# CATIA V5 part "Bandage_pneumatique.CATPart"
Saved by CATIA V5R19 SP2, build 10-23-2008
Part number: Bandage_pneumatique
Bounding box of the stored display mesh (mm): x -331.971 to 331.971, y -970.5 to -729.5, z -331.971 to 331.971
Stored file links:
  G:\EU_thinkMotion\CFAO_2010\MMS_groupe3\MMS_groupe3\pmayet\pmayet_assemblage_animation\pmayet_assemblage_animation\Bandage_pneumatique.CATPart
  G:\EU_thinkMotion\CFAO_2010\MMS_groupe3\MMS_groupe3\pmayet\pmayet_assemblage_animation\pmayet_assemblage_animation\pmayet_assemblage_animation.CATProduct
  G:\EU_thinkMotion\CFAO_2010\MMS_groupe3\MMS_groupe3\pmayet\pmayet_assemblage_animation\pmayet_assemblage_animation\Squelette_porte_moyeu.CATPart
  G:\EU_thinkMotion\CFAO_2010\MMS_groupe3\MMS_groupe3\pmayet\pmayet_assemblage_animation\pmayet_assemblage_animation\Jante.CATPart
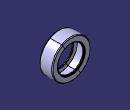
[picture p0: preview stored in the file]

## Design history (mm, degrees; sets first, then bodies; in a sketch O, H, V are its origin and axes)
Parameters
  Longueur_jante = 210 mm
  Rayon_jante = 200 mm
  Epaisseur_jante = 10 mm
Set1
  Plane1: linked copy from another document
  Plane2: linked copy from another document
  DatumCurve1 to DatumCurve5: linked copy from another document
Body1 (main body)
  Sketch1 on Plane1, origin (0, 0, 0), H (0, 1, 0), V (0, 0, 1)
    point P1 (-740, 240)
    line L1 (-742.601, 240) -> (-746.5, 240)
    line L2 (-750.5, 236) -> (-750.5, 226)
    point P2 (-750.5, 226)
    point P3 (-949.5, 223.9503)
    line L3 (-949.5, 223.9503) -> (-949.5, 233.5508)
    line L4 (-953.5, 237.5508) -> (-957.3705, 237.5508)
    point P4 (-960, 237.5508)
    line L5 (-750.019, 332.0507) -> (-950.019, 332.0507)
    point P5 (-740, 332.0507)
    point P6 (-960.1623, 332.0507)
    spline S1 through (-960.1623, 332.0507) (-970.5, 290.0507) (-960, 237.5508)
    spline S2 through (-740, 332.0507) (-729.5, 290.0507) (-740, 240)
    arc A1 centre (-950.019, 317.0507) radius 15 from (-964.1714, 322.0214) to (-950.019, 332.0507) cw
    arc A2 centre (-750.019, 317.0507) radius 15 from (-735.9167, 322.162) to (-750.019, 332.0507) ccw
    arc A3 centre (-742.601, 244) radius 4 from (-742.601, 240) to (-738.929, 242.4138) ccw
    arc A4 centre (-746.5, 236) radius 4 from (-750.5, 236) to (-746.5, 240) cw
    arc A5 centre (-953.5, 233.5508) radius 4 from (-953.5, 237.5508) to (-949.5, 233.5508) cw
    arc A6 centre (-957.3705, 241.5508) radius 4 from (-961.0576, 240) to (-957.3705, 237.5508) ccw
    point P22 (-961.0576, 240)
    reference intersected line E1 through (0, 0) direction (-1, 0) from Plane2
    reference projected line E2 (-949.5, 240) -> (-949.5, -240) from edge of DatumCurve1
    reference intersected line E3 through (0, 0) direction (-1, 0) from Plane2
    reference projected line E4 (-750.5, 240) -> (-750.5, -240) from edge of DatumCurve2
    reference projected line E5 (-949.5, 240) -> (-949.5, -240) from edge of DatumCurve1
    reference projected line E6 (-750.5, 240) -> (-750.5, -240) from edge of DatumCurve2
    reference projected line E7 (-740, 240) -> (-740, -240) from edge of DatumCurve3
    reference projected line E8 (-960, 240) -> (-960, -240) from edge of DatumCurve4
    reference projected line E9 (-740, 240) -> (-740, -240) from edge of DatumCurve3
    point P25 (-960.1623, 332.0507)
    point P26 (-960, 237.5508)
    point P27 (-740, 332.0507)
    point P28 (-740, 240)
    point P29 (-970.5, 290.0507)
    point P30 (-729.5, 290.0507)
    radius A1 = 15
    radius A2 = 15
    radius A3 = 4
    radius A4 = 4
    radius A5 = 4
    radius A6 = 4
    distance E1 P22 = 240 {= Rayon_jante + Epaisseur_jante *4}
    distance P1 E3 = 240 {= Rayon_jante + 4*Epaisseur_jante}
    distance P4 P25 = 94.5 {= 0.45*Longueur_jante}
    distance P29 L5 = 42 {= 0.2*Longueur_jante}
    distance P30 L5 = 42 {= Longueur_jante *0.2}
    distance P29 E5 = 21
    distance P30 E6 = 21
    length L5 = 200 {= Longueur_jante -10mm}
    horizontal: L1 H, L4 H, L5 H
    vertical: L2 V, L3 V
    coincidence: P25 P6, P26 P4, P27 P5, P28 P1, L5 P6, L5 P5, L1 P1, L4 P4, E2 P3, P2 E4, E7 P1, P4 E8, P27 E9
    tangency: A1 S1, A1 L5, A2 S2, A2 L5, A3 L1, A3 S2, A4 L2, A4 L1, A5 L4, A5 L3, A6 S1, A6 L4
  Shaft1: profile Sketch1, axis edge of DatumCurve5, angle 360, thin wall 15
